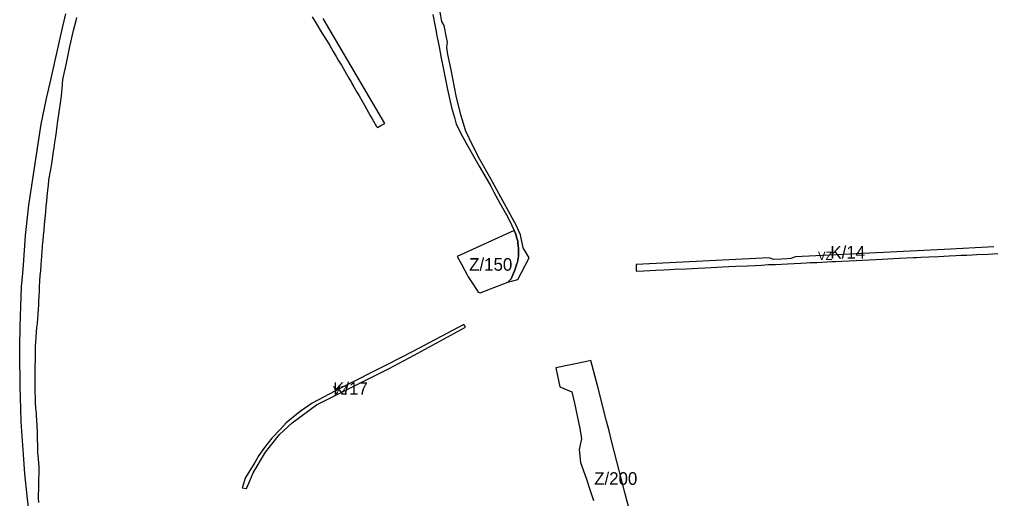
# Model space of a CAD drawing. Extents: x -521939 to -518034, y -1194984 to -1189555.
# Drawn here: x -520854 to -519696, y -1190901 to -1190331 of the extents above; entities that cross this region are included whole.
import ezdxf

# ---------------------------------------------------------------- set-up
doc = ezdxf.new("R2010")
doc.units = 0
for name, color, linetype in [('95420023', 7, 'Continuous'), ('96111023', 7, 'Continuous'), ('96121023', 7, 'Continuous'), ('96202223', 7, 'Continuous')]:
    doc.layers.add(name, color=color, linetype=linetype)

msp = doc.modelspace()

# ---------------------------------------------------------------- linework, layer by layer
at = {"layer": '95420023'}
for points in [[(-520260.36, -1190640.4), (-520246.6, -1190614.37), (-520254.03, -1190602.44), (-520256.94, -1190586.97), (-520261.73, -1190576.17), (-520292.37, -1190520.37), (-520305.38, -1190497.4), (-520313.7, -1190481.31), (-520322.01, -1190463.84), (-520328.19, -1190444.19), (-520333.62, -1190421.51), (-520339.48, -1190390.73), (-520343.5, -1190372.52), (-520344.85, -1190363.88), (-520343.97, -1190357.86), (-520345.06, -1190352.29), (-520347.86, -1190338.07), (-520350.9, -1190332.99), (-520352.86, -1190322.18), (-520363.12, -1190270.76)], [(-520799.14, -1190323.82), (-520803.11, -1190340.79), (-520817.75, -1190406.02)], [(-520786.36, -1190331.78), (-520785.46, -1190328.32)], [(-520361.67, -1190324.78), (-520358.8, -1190339.19), (-520357.64, -1190345.16), (-520356.65, -1190350.44), (-520356.28, -1190352.2), (-520355.24, -1190357.44), (-520354.1, -1190363.35), (-520352.77, -1190370.15), (-520351.48, -1190376.69), (-520349.98, -1190384.24), (-520346.85, -1190400.25), (-520345.34, -1190407.94), (-520344.11, -1190414.17), (-520339.16, -1190435.68), (-520335.69, -1190447.27), (-520333.6, -1190455.52), (-520326.28, -1190470.19), (-520319.79, -1190481.7), (-520313.06, -1190493.24), (-520306.18, -1190505.19), (-520299.49, -1190516.65), (-520292.56, -1190529.3), (-520288.83, -1190536.11), (-520281.56, -1190549.39), (-520273.96, -1190563.31), (-520270.32, -1190570.06), (-520267.58, -1190575.89), (-520264.82, -1190581.96), (-520262.79, -1190586.33), (-520261.69, -1190589.95)], [(-520797.81, -1190382.66), (-520793.77, -1190363.04), (-520789.51, -1190343.91), (-520786.36, -1190331.78)], [(-520802.08, -1190402.34), (-520797.81, -1190382.66)], [(-520817.75, -1190406.02), (-520822, -1190424.77)], [(-520804.05, -1190424.07), (-520803.81, -1190422.46), (-520803.25, -1190415.91), (-520803.04, -1190413.49), (-520802.55, -1190407.76)], [(-520802.55, -1190407.76), (-520802.08, -1190402.34)], [(-520822, -1190424.77), (-520828.37, -1190455.3)], [(-520808.9, -1190457.54), (-520808.05, -1190451.22), (-520807.06, -1190443.91), (-520806.22, -1190438.37), (-520804.98, -1190430.18), (-520804.05, -1190424.07)], [(-520828.37, -1190455.3), (-520842.97, -1190551.61)], [(-520811.63, -1190477.09), (-520810.65, -1190470.17), (-520809.83, -1190464.32)], [(-520809.83, -1190464.32), (-520808.9, -1190457.54)], [(-520814.61, -1190496.95), (-520813.56, -1190490.15), (-520812.54, -1190483.57), (-520811.63, -1190477.09)], [(-520818.67, -1190521.49), (-520816.62, -1190509.25), (-520815.39, -1190501.97), (-520814.61, -1190496.95)], [(-520821.02, -1190541.86), (-520820.91, -1190540.94), (-520820.12, -1190534.01), (-520819.44, -1190528.07), (-520818.73, -1190521.84), (-520818.67, -1190521.49)], [(-520821.91, -1190553.06), (-520821.44, -1190547.14), (-520821.02, -1190541.86)], [(-520842.97, -1190551.61), (-520846.95, -1190587.68)], [(-520824.46, -1190580.91), (-520823.86, -1190574.55), (-520822.46, -1190559.96)], [(-520822.46, -1190559.96), (-520821.91, -1190553.06)], [(-520825.13, -1190587.77), (-520824.56, -1190581.94)], [(-520824.56, -1190581.94), (-520824.46, -1190580.91)], [(-520264.82, -1190581.96), (-520332.64, -1190612.96)], [(-520261.69, -1190589.95), (-520262.79, -1190586.33), (-520264.82, -1190581.96)], [(-520846.95, -1190587.68), (-520849.58, -1190623.3)], [(-520826.28, -1190599.56), (-520825.69, -1190593.61)], [(-520825.69, -1190593.61), (-520825.59, -1190592.55), (-520825.25, -1190589.08)], [(-520825.25, -1190589.08), (-520825.13, -1190587.77)], [(-520260.08, -1190597.14), (-520260.46, -1190594.42), (-520261.69, -1190589.95)], [(-520261.69, -1190589.95), (-520260.46, -1190594.42)], [(-520260.46, -1190594.42), (-520260.08, -1190597.14)], [(-520827.69, -1190617.85), (-520827.28, -1190612.32), (-520826.82, -1190606.09), (-520826.51, -1190601.96), (-520826.28, -1190599.56)], [(-520259.34, -1190604.41), (-520259.34, -1190602.74), (-520260.08, -1190597.14)], [(-520260.08, -1190597.14), (-520259.34, -1190602.74), (-520259.34, -1190604.41)], [(-520259.64, -1190612.41), (-520259.47, -1190611.1), (-520259.34, -1190604.41)], [(-520259.34, -1190604.41), (-520259.47, -1190611.1), (-520259.64, -1190612.41)], [(-520828, -1190622.02), (-520827.69, -1190617.85)], [(-520332.64, -1190612.96), (-520327.5, -1190622.06)], [(-520261.32, -1190621), (-520260.77, -1190619.4), (-520259.64, -1190612.41)], [(-520259.64, -1190612.41), (-520260.77, -1190619.4)], [(-520849.58, -1190623.3), (-520850.63, -1190636.95)], [(-520829, -1190635.46), (-520828.79, -1190632.68), (-520828.59, -1190629.93), (-520828.13, -1190623.75)], [(-520828.13, -1190623.75), (-520828, -1190622.02)], [(-520327.5, -1190622.06), (-520323.87, -1190628.67)], [(-520323.87, -1190628.67), (-520320.59, -1190634.65)], [(-520272.31, -1190643.28), (-520268.22, -1190639.47), (-520263.6, -1190628.04)], [(-520263.6, -1190628.04), (-520268.22, -1190639.47)], [(-520263.6, -1190628.04), (-520261.32, -1190621)], [(-520261.32, -1190621), (-520263.6, -1190628.04)], [(-520260.77, -1190619.4), (-520261.32, -1190621)], [(-520850.63, -1190636.95), (-520851.64, -1190648.56)], [(-520830.09, -1190653.98), (-520829.81, -1190648.4), (-520829.5, -1190642.29), (-520829.49, -1190642.08)], [(-520829.49, -1190642.08), (-520829, -1190635.46)], [(-520320.59, -1190634.65), (-520319.31, -1190636.97), (-520317.05, -1190640.57)], [(-520317.05, -1190640.57), (-520313.14, -1190646.59)], [(-520268.22, -1190639.47), (-520272.31, -1190643.28)], [(-520272.31, -1190643.28), (-520260.36, -1190640.4)], [(-520851.64, -1190648.56), (-520852.28, -1190660.73)], [(-520313.14, -1190646.59), (-520310.32, -1190651.11)], [(-520310.32, -1190651.11), (-520307.46, -1190655.43)], [(-520307.46, -1190655.43), (-520305.17, -1190656.12), (-520292.86, -1190651.31), (-520272.31, -1190643.28)], [(-520852.28, -1190660.73), (-520852.56, -1190672.24)], [(-520830.95, -1190670.95), (-520830.65, -1190664.99)], [(-520830.65, -1190664.99), (-520830.5, -1190662.17), (-520830.37, -1190659.51), (-520830.09, -1190653.98)], [(-520852.56, -1190672.24), (-520852.94, -1190683.51)], [(-520831.92, -1190686.11), (-520831.53, -1190682.22), (-520831.48, -1190681.4), (-520831.18, -1190675.42)], [(-520831.18, -1190675.42), (-520830.95, -1190670.95)], [(-520852.94, -1190683.51), (-520853.37, -1190697.08)], [(-520834.57, -1190720.65), (-520834.19, -1190713.84), (-520833.93, -1190709.32), (-520833.53, -1190702.3), (-520833.06, -1190697.52), (-520832.56, -1190692.51), (-520831.92, -1190686.11)], [(-520853.37, -1190697.08), (-520853.44, -1190702.35)], [(-520853.44, -1190702.35), (-520853.63, -1190713.88)], [(-520853.79, -1190723.11), (-520853.87, -1190735.1)], [(-520853.63, -1190713.88), (-520853.79, -1190723.11)], [(-520835.02, -1190749.26), (-520834.99, -1190743.76), (-520834.99, -1190742.61), (-520834.91, -1190737.42), (-520834.82, -1190731.68), (-520834.72, -1190725.53), (-520834.67, -1190722.46)], [(-520834.67, -1190722.46), (-520834.57, -1190720.65)], [(-520853.87, -1190735.1), (-520853.81, -1190743.83)], [(-520853.81, -1190743.83), (-520853.6, -1190752.22)], [(-520179.93, -1190738.09), (-520214.93, -1190745.28)], [(-520214.93, -1190745.28), (-520210.17, -1190768.14)], [(-520173.21, -1190736.7), (-520179.93, -1190738.09)], [(-520165.15, -1190767.99), (-520173.21, -1190736.7)], [(-520853.6, -1190752.22), (-520853.48, -1190767.88)], [(-520835.08, -1190762.16), (-520835.05, -1190756.12)], [(-520835.05, -1190756.12), (-520835.02, -1190749.26)], [(-520853.48, -1190767.88), (-520852.66, -1190794.34)], [(-520835.08, -1190762.45), (-520835.08, -1190762.16)], [(-520835.08, -1190762.76), (-520835.08, -1190762.45)], [(-520834.99, -1190774.65), (-520835.04, -1190768.27), (-520835.08, -1190762.76)], [(-520210.17, -1190768.14), (-520195.82, -1190773.79)], [(-520154.72, -1190808.75), (-520165.15, -1190767.99)], [(-520834.94, -1190780.45), (-520834.99, -1190774.65)], [(-520834.92, -1190782.92), (-520834.94, -1190780.45)], [(-520195.82, -1190773.79), (-520192.9, -1190787.25)], [(-520833.91, -1190796.45), (-520834.16, -1190793.02), (-520834.61, -1190787.07), (-520834.92, -1190782.92)], [(-520192.9, -1190787.25), (-520189.71, -1190802.47)], [(-520852.66, -1190794.34), (-520852.06, -1190809.58)], [(-520833.68, -1190799.5), (-520833.91, -1190796.45)], [(-520833.41, -1190803.07), (-520833.68, -1190799.5)], [(-520833.2, -1190807.31), (-520833.41, -1190803.07)], [(-520189.71, -1190802.47), (-520186.5, -1190817.43)], [(-520852.06, -1190809.58), (-520849.49, -1190848.58)], [(-520832.83, -1190814.81), (-520833.2, -1190807.31)], [(-520832.46, -1190822.22), (-520832.83, -1190814.81)], [(-520151.61, -1190820.43), (-520154.72, -1190808.75)], [(-520832.02, -1190843.31), (-520832.12, -1190838.18), (-520832.28, -1190829.94), (-520832.41, -1190823.17), (-520832.46, -1190822.22)], [(-520186.5, -1190817.43), (-520184.56, -1190829.71)], [(-520148.53, -1190832.37), (-520151.61, -1190820.43)], [(-520184.56, -1190829.71), (-520187.09, -1190842.73)], [(-520132.72, -1190893.53), (-520148.53, -1190832.37)], [(-520849.49, -1190848.58), (-520847.98, -1190871.46), (-520845.07, -1190897.78)], [(-520831.79, -1190846.02), (-520832.02, -1190843.31)], [(-520831.11, -1190853.75), (-520831.79, -1190846.02)], [(-520187.09, -1190842.73), (-520185.78, -1190857.9)], [(-520830.42, -1190870.43), (-520830.27, -1190863.43), (-520831.11, -1190853.75)], [(-520185.78, -1190857.9), (-520178.77, -1190876.6)], [(-520831.02, -1190897.74), (-520830.82, -1190888.52), (-520830.61, -1190878.92), (-520830.42, -1190870.43)], [(-520178.77, -1190876.6), (-520174.75, -1190888.89)], [(-520174.75, -1190888.89), (-520170.2, -1190903.06)], [(-520124.37, -1190925.82), (-520132.72, -1190893.53)], [(-520845.07, -1190897.78), (-520843.48, -1190911.63)], [(-520831.08, -1190900.46), (-520831.02, -1190897.74)], [(-520830.74, -1190905.71), (-520831.08, -1190900.46)]]:
    msp.add_lwpolyline(points, dxfattribs=at)
at = {"layer": '96111023'}
for points in [[(-520505.06, -1190327.7), (-520500.89, -1190334.53)], [(-520500.89, -1190334.53), (-520493.14, -1190347.28)], [(-520418.63, -1190454.51), (-520492.06, -1190329.61)], [(-520493.14, -1190347.28), (-520487.23, -1190356.63)], [(-520487.23, -1190356.63), (-520484.26, -1190361.73)], [(-520484.26, -1190361.73), (-520480.03, -1190368.97)], [(-520480.03, -1190368.97), (-520476.65, -1190374.74)], [(-520476.65, -1190374.74), (-520474.06, -1190379.19)], [(-520474.06, -1190379.19), (-520470.42, -1190385.29)], [(-520470.42, -1190385.29), (-520464.79, -1190395.13)], [(-520464.79, -1190395.13), (-520461.6, -1190400.68)], [(-520461.6, -1190400.68), (-520458.54, -1190405.84)], [(-520458.54, -1190405.84), (-520457.88, -1190406.97)], [(-520457.88, -1190406.97), (-520455.54, -1190411.02)], [(-520455.54, -1190411.02), (-520452.05, -1190417.09)], [(-520452.05, -1190417.09), (-520449.33, -1190421.77)], [(-520449.33, -1190421.77), (-520446.15, -1190427.25)], [(-520446.15, -1190427.25), (-520442.94, -1190432.82)], [(-520442.94, -1190432.82), (-520435.78, -1190445.73)], [(-520435.78, -1190445.73), (-520433.93, -1190449.11), (-520431.58, -1190452.47)], [(-520431.58, -1190452.47), (-520428.66, -1190458.29), (-520427.37, -1190459.39)], [(-520423.37, -1190457.05), (-520418.63, -1190454.51)], [(-520427.37, -1190459.39), (-520423.37, -1190457.05)], [(-519693.24, -1190601.52), (-519752.34, -1190604.4), (-519929.64, -1190613.04), (-519935.19, -1190615.32), (-519939.78, -1190615.54)], [(-519955.34, -1190616.3), (-519961.08, -1190614.58), (-520119.28, -1190622.29)], [(-519946.03, -1190615.85), (-519955.34, -1190616.3)], [(-519939.78, -1190615.54), (-519946.03, -1190615.85)], [(-519904.19, -1190619.79), (-519886.32, -1190618.93)], [(-519886.32, -1190618.93), (-519881.51, -1190618.7)], [(-519881.51, -1190618.7), (-519874.3, -1190618.35)], [(-519874.3, -1190618.35), (-519857.39, -1190617.5)], [(-519857.39, -1190617.5), (-519842, -1190616.75)], [(-519842, -1190616.75), (-519826.46, -1190615.97)], [(-519826.46, -1190615.97), (-519806.02, -1190614.98)], [(-519806.02, -1190614.98), (-519789.16, -1190614.2)], [(-519789.16, -1190614.2), (-519785.45, -1190613.97)], [(-519785.45, -1190613.97), (-519780.36, -1190613.76)], [(-519780.36, -1190613.76), (-519770.89, -1190613.31)], [(-519770.89, -1190613.31), (-519759.09, -1190612.73)], [(-519759.09, -1190612.73), (-519746.72, -1190612.13)], [(-519746.72, -1190612.13), (-519738.62, -1190611.73)], [(-519738.62, -1190611.73), (-519732.39, -1190611.44)], [(-519732.39, -1190611.44), (-519725.37, -1190611.1)], [(-519725.37, -1190611.1), (-519719.21, -1190610.77)], [(-519719.21, -1190610.77), (-519713.65, -1190610.53)], [(-519713.65, -1190610.53), (-519700.36, -1190609.88)], [(-519700.36, -1190609.88), (-519688.65, -1190609.3)], [(-520119.28, -1190622.29), (-520119.46, -1190630.32)], [(-520119.46, -1190630.32), (-520110.38, -1190629.91)], [(-520110.38, -1190629.91), (-520102.91, -1190629.55)], [(-520102.91, -1190629.55), (-520095.81, -1190629.12)], [(-520095.81, -1190629.12), (-520086.43, -1190628.7)], [(-520086.43, -1190628.7), (-520078.68, -1190628.32)], [(-520078.68, -1190628.32), (-520074.1, -1190628.1)], [(-520074.1, -1190628.1), (-520059.37, -1190627.38)], [(-520059.37, -1190627.38), (-520045.77, -1190626.72)], [(-520045.77, -1190626.72), (-520037.2, -1190626.26)], [(-520037.2, -1190626.26), (-520030.12, -1190625.96)], [(-520030.12, -1190625.96), (-520023.13, -1190625.6)], [(-520023.13, -1190625.6), (-520016.69, -1190625.32)], [(-520016.69, -1190625.32), (-520008.95, -1190624.91)], [(-520008.95, -1190624.91), (-520000.46, -1190624.51)], [(-520000.46, -1190624.51), (-519986.76, -1190623.81)], [(-519986.76, -1190623.81), (-519977.56, -1190623.39)], [(-519977.56, -1190623.39), (-519970.21, -1190623.03)], [(-519970.21, -1190623.03), (-519961.73, -1190622.55)], [(-519961.73, -1190622.55), (-519953.25, -1190622.2)], [(-519953.25, -1190622.2), (-519938.98, -1190621.52)], [(-519938.98, -1190621.52), (-519923.22, -1190620.76)], [(-519923.22, -1190620.76), (-519916.75, -1190620.41)], [(-519916.75, -1190620.41), (-519912.12, -1190620.15)], [(-519912.12, -1190620.15), (-519904.19, -1190619.79)], [(-520579.33, -1190879.67), (-520575.39, -1190870.36), (-520560.86, -1190845.88), (-520544.03, -1190824.72), (-520528.99, -1190810.95), (-520500.11, -1190789.41), (-520469.27, -1190773.73), (-520413.62, -1190746.07), (-520383.85, -1190730.39), (-520322.54, -1190696.8), (-520323.5, -1190695.35)], [(-520324.46, -1190693.89), (-520386.14, -1190726.13)], [(-520323.5, -1190695.35), (-520324.46, -1190693.89)], [(-520386.14, -1190726.13), (-520415.61, -1190741.57)], [(-520415.61, -1190741.57), (-520471.38, -1190769.62), (-520505.39, -1190787.53)], [(-520505.39, -1190787.53), (-520519.61, -1190797.43), (-520536.03, -1190811)], [(-520536.03, -1190811), (-520543.12, -1190818.16)], [(-520543.12, -1190818.16), (-520553.22, -1190828.97)], [(-520553.22, -1190828.97), (-520562.17, -1190840.06)], [(-520562.17, -1190840.06), (-520568.69, -1190849.57), (-520573.57, -1190857.84)], [(-520573.57, -1190857.84), (-520584.48, -1190876.05)], [(-520584.48, -1190876.05), (-520588.66, -1190888.36)], [(-520583.27, -1190888.97), (-520579.33, -1190879.67)], [(-520588.66, -1190888.36), (-520583.27, -1190888.97)]]:
    msp.add_lwpolyline(points, dxfattribs=at)
at = {"layer": '96121023'}
for points in [[(-520260.36, -1190640.4), (-520246.6, -1190614.37), (-520254.03, -1190602.44), (-520256.94, -1190586.97), (-520261.73, -1190576.17), (-520292.37, -1190520.37), (-520305.38, -1190497.4), (-520313.7, -1190481.31), (-520322.01, -1190463.84), (-520328.19, -1190444.19), (-520333.62, -1190421.51), (-520339.48, -1190390.73), (-520343.5, -1190372.52), (-520344.85, -1190363.88), (-520343.97, -1190357.86), (-520345.06, -1190352.29), (-520347.86, -1190338.07), (-520350.9, -1190332.99), (-520352.86, -1190322.18), (-520363.12, -1190270.76)], [(-520361.67, -1190324.78), (-520358.8, -1190339.19), (-520357.64, -1190345.16), (-520356.65, -1190350.44), (-520356.28, -1190352.2), (-520355.24, -1190357.44), (-520354.1, -1190363.35), (-520352.77, -1190370.15), (-520351.48, -1190376.69), (-520349.98, -1190384.24), (-520346.85, -1190400.25), (-520345.34, -1190407.94), (-520344.11, -1190414.17), (-520339.16, -1190435.68), (-520335.69, -1190447.27), (-520333.6, -1190455.52), (-520326.28, -1190470.19), (-520319.79, -1190481.7), (-520313.06, -1190493.24), (-520306.18, -1190505.19), (-520299.49, -1190516.65), (-520292.56, -1190529.3), (-520288.83, -1190536.11), (-520281.56, -1190549.39), (-520273.96, -1190563.31), (-520270.32, -1190570.06), (-520267.58, -1190575.89), (-520264.82, -1190581.96), (-520262.79, -1190586.33), (-520261.69, -1190589.95)], [(-520261.69, -1190589.95), (-520260.46, -1190594.42)], [(-520260.46, -1190594.42), (-520260.08, -1190597.14)], [(-520260.08, -1190597.14), (-520259.34, -1190602.74)], [(-520259.34, -1190604.41), (-520259.47, -1190611.1)], [(-520259.34, -1190602.74), (-520259.34, -1190604.41)], [(-520259.64, -1190612.41), (-520260.77, -1190619.4)], [(-520259.47, -1190611.1), (-520259.64, -1190612.41)], [(-520263.6, -1190628.04), (-520268.22, -1190639.47)], [(-520261.32, -1190621), (-520263.6, -1190628.04)], [(-520260.77, -1190619.4), (-520261.32, -1190621)], [(-520268.22, -1190639.47), (-520272.31, -1190643.28)], [(-520272.31, -1190643.28), (-520260.36, -1190640.4)]]:
    msp.add_lwpolyline(points, dxfattribs=at)
at = {"layer": '96202223'}
for points in [[(-520505.06, -1190327.7), (-520500.89, -1190334.53)], [(-520500.89, -1190334.53), (-520493.14, -1190347.28)], [(-520418.63, -1190454.51), (-520492.06, -1190329.61)], [(-520493.14, -1190347.28), (-520487.23, -1190356.63)], [(-520487.23, -1190356.63), (-520484.26, -1190361.73)], [(-520484.26, -1190361.73), (-520480.03, -1190368.97)], [(-520480.03, -1190368.97), (-520476.65, -1190374.74)], [(-520476.65, -1190374.74), (-520474.06, -1190379.19)], [(-520474.06, -1190379.19), (-520470.42, -1190385.29)], [(-520470.42, -1190385.29), (-520464.79, -1190395.13)], [(-520464.79, -1190395.13), (-520461.6, -1190400.68)], [(-520461.6, -1190400.68), (-520458.54, -1190405.84)], [(-520458.54, -1190405.84), (-520457.88, -1190406.97)], [(-520457.88, -1190406.97), (-520455.54, -1190411.02)], [(-520455.54, -1190411.02), (-520452.05, -1190417.09)], [(-520452.05, -1190417.09), (-520449.33, -1190421.77)], [(-520449.33, -1190421.77), (-520446.15, -1190427.25)], [(-520446.15, -1190427.25), (-520442.94, -1190432.82)], [(-520442.94, -1190432.82), (-520435.78, -1190445.73)], [(-520435.78, -1190445.73), (-520433.93, -1190449.11), (-520431.58, -1190452.47)], [(-520431.58, -1190452.47), (-520428.66, -1190458.29), (-520427.37, -1190459.39)], [(-520423.37, -1190457.05), (-520418.63, -1190454.51)], [(-520427.37, -1190459.39), (-520423.37, -1190457.05)], [(-519693.24, -1190601.52), (-519752.34, -1190604.4), (-519929.64, -1190613.04), (-519935.19, -1190615.32), (-519939.78, -1190615.54)], [(-519955.34, -1190616.3), (-519961.08, -1190614.58), (-520119.28, -1190622.29)], [(-519946.03, -1190615.85), (-519955.34, -1190616.3)], [(-519939.78, -1190615.54), (-519946.03, -1190615.85)], [(-519904.19, -1190619.79), (-519886.32, -1190618.93)], [(-519886.32, -1190618.93), (-519881.51, -1190618.7)], [(-519881.51, -1190618.7), (-519874.3, -1190618.35)], [(-519874.3, -1190618.35), (-519857.39, -1190617.5)], [(-519857.39, -1190617.5), (-519842, -1190616.75)], [(-519842, -1190616.75), (-519826.46, -1190615.97)], [(-519826.46, -1190615.97), (-519806.02, -1190614.98)], [(-519806.02, -1190614.98), (-519789.16, -1190614.2)], [(-519789.16, -1190614.2), (-519785.45, -1190613.97)], [(-519785.45, -1190613.97), (-519780.36, -1190613.76)], [(-519780.36, -1190613.76), (-519770.89, -1190613.31)], [(-519770.89, -1190613.31), (-519759.09, -1190612.73)], [(-519759.09, -1190612.73), (-519746.72, -1190612.13)], [(-519746.72, -1190612.13), (-519738.62, -1190611.73)], [(-519738.62, -1190611.73), (-519732.39, -1190611.44)], [(-519732.39, -1190611.44), (-519725.37, -1190611.1)], [(-519725.37, -1190611.1), (-519719.21, -1190610.77)], [(-519719.21, -1190610.77), (-519713.65, -1190610.53)], [(-519713.65, -1190610.53), (-519700.36, -1190609.88)], [(-519700.36, -1190609.88), (-519688.65, -1190609.3)], [(-520119.28, -1190622.29), (-520119.46, -1190630.32)], [(-520119.46, -1190630.32), (-520110.38, -1190629.91)], [(-520110.38, -1190629.91), (-520102.91, -1190629.55)], [(-520102.91, -1190629.55), (-520095.81, -1190629.12)], [(-520095.81, -1190629.12), (-520086.43, -1190628.7)], [(-520086.43, -1190628.7), (-520078.68, -1190628.32)], [(-520078.68, -1190628.32), (-520074.1, -1190628.1)], [(-520074.1, -1190628.1), (-520059.37, -1190627.38)], [(-520059.37, -1190627.38), (-520045.77, -1190626.72)], [(-520045.77, -1190626.72), (-520037.2, -1190626.26)], [(-520037.2, -1190626.26), (-520030.12, -1190625.96)], [(-520030.12, -1190625.96), (-520023.13, -1190625.6)], [(-520023.13, -1190625.6), (-520016.69, -1190625.32)], [(-520016.69, -1190625.32), (-520008.95, -1190624.91)], [(-520008.95, -1190624.91), (-520000.46, -1190624.51)], [(-520000.46, -1190624.51), (-519986.76, -1190623.81)], [(-519986.76, -1190623.81), (-519977.56, -1190623.39)], [(-519977.56, -1190623.39), (-519970.21, -1190623.03)], [(-519970.21, -1190623.03), (-519961.73, -1190622.55)], [(-519961.73, -1190622.55), (-519953.25, -1190622.2)], [(-519953.25, -1190622.2), (-519938.98, -1190621.52)], [(-519938.98, -1190621.52), (-519923.22, -1190620.76)], [(-519923.22, -1190620.76), (-519916.75, -1190620.41)], [(-519916.75, -1190620.41), (-519912.12, -1190620.15)], [(-519912.12, -1190620.15), (-519904.19, -1190619.79)], [(-520579.33, -1190879.67), (-520575.39, -1190870.36), (-520560.86, -1190845.88), (-520544.03, -1190824.72), (-520528.99, -1190810.95), (-520500.11, -1190789.41), (-520469.27, -1190773.73), (-520413.62, -1190746.07), (-520383.85, -1190730.39), (-520322.54, -1190696.8), (-520323.5, -1190695.35)], [(-520324.46, -1190693.89), (-520386.14, -1190726.13)], [(-520323.5, -1190695.35), (-520324.46, -1190693.89)], [(-520386.14, -1190726.13), (-520415.61, -1190741.57)], [(-520415.61, -1190741.57), (-520471.38, -1190769.62), (-520505.39, -1190787.53)], [(-520505.39, -1190787.53), (-520519.61, -1190797.43), (-520536.03, -1190811)], [(-520536.03, -1190811), (-520543.12, -1190818.16)], [(-520543.12, -1190818.16), (-520553.22, -1190828.97)], [(-520553.22, -1190828.97), (-520562.17, -1190840.06)], [(-520562.17, -1190840.06), (-520568.69, -1190849.57), (-520573.57, -1190857.84)], [(-520573.57, -1190857.84), (-520584.48, -1190876.05)], [(-520584.48, -1190876.05), (-520588.66, -1190888.36)], [(-520583.27, -1190888.97), (-520579.33, -1190879.67)], [(-520588.66, -1190888.36), (-520583.27, -1190888.97)]]:
    msp.add_lwpolyline(points, dxfattribs=at)

# ---------------------------------------------------------------- texts
at = {"layer": '95420023'}
for s, rotation, p in [('Z/150', 0, (-520318.18, -1190629.75)), ('Z/200', 360, (-520169.26, -1190884.59))]:
    msp.add_text(s, height=15, rotation=rotation, dxfattribs=at).set_placement(p)
at = {"layer": '96111023'}
for s, p in [('K/14', (-519887.97, -1190615.39)), ('K/17', (-520480.22, -1190777.46))]:
    msp.add_text(s, height=15, rotation=360, dxfattribs=at).set_placement(p)
at = {"layer": '96202223'}
for rotation, p in [(0, (-519902.76, -1190617.11)), (360, (-520480.37, -1190776.81))]:
    msp.add_text('VZ', height=10, rotation=rotation, dxfattribs=at).set_placement(p)

doc.saveas('drawing.dxf')
